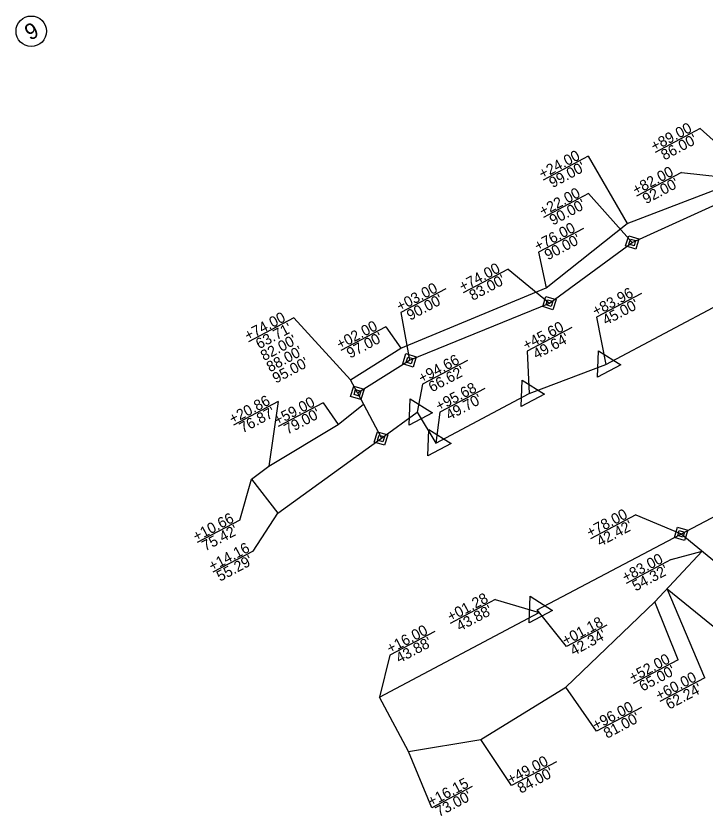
# Model space of a CAD drawing. Extents: x 1487704 to 1489071, y 498271 to 499440.
# Drawn here: x 1487703.5 to 1488029.1, y 498303.4 to 498681.2 of the extents above; entities that cross this region are included whole.
import ezdxf

# ---------------------------------------------------------------- set-up
doc = ezdxf.new("R2010")
doc.units = 0
for name, color, linetype in [('Prop Easement Construction', 7, 'Continuous'), ('Prop Easement Construction Station Offsets', 7, 'Continuous'), ('Prop Easement Permanent Drainage', 7, 'Continuous'), ('Prop Easement Permanent Drainage Station Offsets', 7, 'Continuous'), ('Prop Easement Temporary Drainage', 7, 'Continuous'), ('Prop Easement Temporary Drainage Station Offsets', 7, 'Continuous'), ('Prop ROW Marker CELL', 7, 'Continuous'), ('Prop ROW Permanent Easement CELL', 7, 'Continuous'), ('Prop ROW RW Lines', 7, 'Continuous'), ('Prop ROW Station Offsets', 7, 'Continuous'), ('Prop ROW Text', 7, 'Continuous')]:
    doc.layers.add(name, color=color, linetype=linetype)

msp = doc.modelspace()

# ---------------------------------------------------------------- linework, layer by layer
at = {"layer": 'Prop Easement Construction'}
for p, q in [((1487855.79, 498488.32), (1487867.65, 498497.99)), ((1487823.08, 498468.59), (1487855.79, 498488.32)), ((1487827.26, 498446.38), (1487876.21, 498481.82)), ((1487814.75, 498462.54), (1487823.08, 498468.59)), ((1487814.75, 498462.54), (1487827.26, 498446.38)), ((1488005.36, 498404.56), (1488027.76, 498428.5)), ((1487963.35, 498364.22), (1488005.36, 498404.56)), ((1487950.65, 498399.5), (1487949.84, 498400.81)), ((1487875.28, 498359.6), (1487950.65, 498399.5)), ((1487923.22, 498339.58), (1487963.35, 498364.22)), ((1487889.04, 498333.93), (1487875.28, 498359.6)), ((1487889.04, 498333.93), (1487923.22, 498339.58))]:
    msp.add_line(p, q, dxfattribs=at)
at = {"layer": 'Prop Easement Construction Station Offsets'}
for p, q in [((1487827.42, 498499.21), (1487806.24, 498488.02)), ((1487848.63, 498498.56), (1487827.37, 498487.33)), ((1487809.23, 498443.15), (1487789.11, 498432.53)), ((1487815.65, 498428.57), (1487796.59, 498418.51)), ((1488013.11, 498424.55), (1487991.86, 498413.3)), ((1487929.99, 498405.65), (1487908.74, 498394.4)), ((1487929.99, 498405.65), (1487950.65, 498399.5)), ((1487901.42, 498390.56), (1487880.17, 498379.31)), ((1487880.17, 498379.31), (1487875.28, 498359.6)), ((1488016.41, 498377.24), (1487995.16, 498365.99)), ((1487999.08, 498354.69), (1487977.82, 498343.44)), ((1487958.86, 498329.03), (1487937.61, 498317.77)), ((1487919.03, 498317.37), (1487900.02, 498307.34))]:
    msp.add_line(p, q, dxfattribs=at)
for points in [[(1487827.42, 498499.21), (1487823.08, 498468.59)], [(1487848.63, 498498.56), (1487855.79, 498488.32)], [(1487809.23, 498443.15), (1487814.75, 498462.54)], [(1487815.65, 498428.57), (1487827.26, 498446.38)], [(1488013.11, 498424.55), (1488027.76, 498428.5)], [(1488016.41, 498377.24), (1488005.36, 498404.56)], [(1487977.82, 498343.44), (1487963.35, 498364.22)], [(1487937.61, 498317.77), (1487923.22, 498339.58)], [(1487900.02, 498307.34), (1487889.04, 498333.93)]]:
    msp.add_lwpolyline(points, dxfattribs=at)
at = {"layer": 'Prop Easement Permanent Drainage'}
for p, q in [((1487994.71, 498574.3), (1488055.79, 498602.11)), ((1487955.56, 498545.66), (1487994.71, 498574.3)), ((1487889.53, 498518.63), (1487955.56, 498545.66)), ((1487864.84, 498503.29), (1487889.53, 498518.63)), ((1487864.84, 498503.29), (1487876.21, 498481.82)), ((1487876.21, 498481.82), (1487893.1, 498494.07)), ((1488017.78, 498436.68), (1488099.66, 498369.62))]:
    msp.add_line(p, q, dxfattribs=at)
at = {"layer": 'Prop Easement Permanent Drainage Station Offsets'}
for p, q in [((1488026.73, 498628.03), (1488005.46, 498616.8)), ((1487974.02, 498597.33), (1487952.76, 498586.1)), ((1487936.13, 498561.75), (1487914.87, 498550.53)), ((1487906.59, 498552.41), (1487885.32, 498541.18)), ((1487996.32, 498445.62), (1487975.05, 498434.39))]:
    msp.add_line(p, q, dxfattribs=at)
for points in [[(1488026.73, 498628.03), (1488055.79, 498602.11)], [(1487974.02, 498597.33), (1487994.71, 498574.3)], [(1487936.13, 498561.75), (1487955.56, 498545.66)], [(1487885.32, 498541.18), (1487889.53, 498518.63)], [(1487996.32, 498445.62), (1488017.78, 498436.68), (1488017.78, 498436.68)]]:
    msp.add_lwpolyline(points, dxfattribs=at)
at = {"layer": 'Prop Easement Temporary Drainage'}
for p, q in [((1487992.26, 498583.19), (1488046.8, 498604.14)), ((1487954.05, 498552.78), (1487992.26, 498583.19)), ((1487885.38, 498524.34), (1487954.05, 498552.78)), ((1487861.56, 498509.48), (1487885.38, 498524.34)), ((1487864.84, 498503.29), (1487861.56, 498509.48)), ((1488011.14, 498410.74), (1488060.72, 498370.51))]:
    msp.add_line(p, q, dxfattribs=at)
at = {"layer": 'Prop Easement Temporary Drainage Station Offsets'}
for p, q in [((1487973.86, 498615), (1487952.59, 498603.77)), ((1488018.02, 498607.38), (1487996.76, 498596.15)), ((1487971.68, 498580.88), (1487950.42, 498569.65)), ((1487834.87, 498538.67), (1487813.35, 498527.3)), ((1487878.21, 498534.5), (1487856.95, 498523.27)), ((1488028.97, 498368.67), (1488007.7, 498357.44))]:
    msp.add_line(p, q, dxfattribs=at)
for points in [[(1487973.86, 498615), (1487992.26, 498583.19)], [(1488018.02, 498607.38), (1488046.8, 498604.14)], [(1487950.42, 498569.65), (1487954.05, 498552.78), (1487954.05, 498552.78)], [(1487834.87, 498538.67), (1487861.56, 498509.48), (1487861.56, 498509.48)], [(1487878.21, 498534.5), (1487885.38, 498524.34)], [(1488028.97, 498368.67), (1488011.14, 498410.74)]]:
    msp.add_lwpolyline(points, dxfattribs=at)
at = {"layer": 'Prop ROW Marker CELL'}
for p, q in [((1487994.71, 498574.3), (1487994.71, 498574.3)), ((1487955.56, 498545.66), (1487955.56, 498545.66)), ((1487889.48, 498518.59), (1487889.48, 498518.59)), ((1487982.15, 498516.73), (1487982.15, 498516.73)), ((1487864.84, 498503.29), (1487864.84, 498503.29)), ((1487946.07, 498502.89), (1487946.07, 498502.89)), ((1487893.1, 498494.07), (1487893.1, 498494.07)), ((1487876.01, 498481.68), (1487876.01, 498481.68)), ((1487901.92, 498479.58), (1487901.92, 498479.58)), ((1488017.78, 498436.68), (1488017.78, 498436.68)), ((1487949.84, 498400.81), (1487949.84, 498400.81))]:
    msp.add_line(p, q, dxfattribs=at)
for points in [[(1487978.3, 498510.63), (1487978.78, 498523.1), (1487989.35, 498516.47)], [(1487942.22, 498496.79), (1487942.71, 498509.26), (1487953.28, 498502.63)], [(1487889.26, 498487.97), (1487889.74, 498500.43), (1487900.31, 498493.8)], [(1487898.07, 498473.48), (1487898.56, 498485.95), (1487909.13, 498479.31)], [(1487945.99, 498394.7), (1487946.48, 498407.17), (1487957.05, 498400.54)]]:
    msp.add_lwpolyline(points, close=True, dxfattribs=at)
at = {"layer": 'Prop ROW Permanent Easement CELL'}
for points in [[(1487993.03, 498577.48), (1487997.89, 498575.98), (1487996.39, 498571.12), (1487991.52, 498572.62)], [(1487993.87, 498575.89), (1487996.3, 498575.14), (1487995.55, 498572.71), (1487993.12, 498573.46)], [(1487953.88, 498548.84), (1487958.74, 498547.34), (1487957.24, 498542.47), (1487952.38, 498543.98)], [(1487954.72, 498547.25), (1487957.15, 498546.5), (1487956.4, 498544.07), (1487953.97, 498544.82)], [(1487887.8, 498521.78), (1487892.66, 498520.27), (1487891.16, 498515.41), (1487886.3, 498516.91)], [(1487888.64, 498520.18), (1487891.07, 498519.43), (1487890.32, 498517), (1487887.89, 498517.75)], [(1487863.16, 498506.47), (1487868.02, 498504.97), (1487866.52, 498500.11), (1487861.66, 498501.61)], [(1487864, 498504.88), (1487866.43, 498504.13), (1487865.68, 498501.7), (1487863.25, 498502.45)], [(1487874.33, 498484.86), (1487879.19, 498483.36), (1487877.69, 498478.49), (1487872.82, 498480)], [(1487875.17, 498483.27), (1487877.6, 498482.52), (1487876.85, 498480.09), (1487874.41, 498480.84)], [(1488016.09, 498439.86), (1488020.96, 498438.36), (1488019.46, 498433.49), (1488014.59, 498435)], [(1488016.93, 498438.27), (1488019.37, 498437.52), (1488018.62, 498435.09), (1488016.18, 498435.84)]]:
    msp.add_lwpolyline(points, close=True, dxfattribs=at)
at = {"layer": 'Prop ROW RW Lines'}
for p, q in [((1487982.15, 498516.73), (1488093.99, 498575.94)), ((1487946.07, 498502.89), (1487982.15, 498516.73)), ((1487901.92, 498479.58), (1487946.07, 498502.89)), ((1487893.1, 498494.07), (1487901.92, 498479.58)), ((1487949.84, 498400.81), (1488123.26, 498492.38))]:
    msp.add_line(p, q, dxfattribs=at)
at = {"layer": 'Prop ROW Station Offsets'}
for p, q in [((1487999.02, 498550.11), (1487977.84, 498538.93)), ((1487977.84, 498538.93), (1487982.15, 498516.73)), ((1487966.2, 498534.08), (1487945.02, 498522.9)), ((1487945.02, 498522.9), (1487946.07, 498502.89)), ((1487916.85, 498518.51), (1487895.68, 498507.3)), ((1487925, 498505.31), (1487903.82, 498494.1)), ((1487982.64, 498393.52), (1487963.58, 498383.43))]:
    msp.add_line(p, q, dxfattribs=at)
for points in [[(1487895.68, 498507.3), (1487893.1, 498494.07)], [(1487903.82, 498494.1), (1487901.92, 498479.58)], [(1487963.58, 498383.43), (1487949.84, 498400.81)]]:
    msp.add_lwpolyline(points, dxfattribs=at)
at = {"layer": 'Prop ROW Text'}
msp.add_line((1487710.75, 498674.03), (1487710.75, 498674.03), dxfattribs=at)
msp.add_circle((1487710.75, 498674.03), 7.2, dxfattribs=at)

# ---------------------------------------------------------------- texts
at = {"layer": 'Prop Easement Construction Station Offsets'}
for s, rotation, p in [('+20.86', 27.8351, (1487805.85, 498488.38)), ('+59.00', 27.8351, (1487827, 498487.7)), ("76.87'", 27.8351, (1487810.66, 498484.14)), ("79.00'", 27.8351, (1487831.83, 498483.46)), ('+10.66', 27.8351, (1487788.71, 498432.89)), ("75.42'", 27.8351, (1487792.99, 498428.36)), ('+14.16', 27.8351, (1487796.2, 498418.87)), ("55.29'", 27.8351, (1487799.95, 498414.06)), ('+83.00', 27.895, (1487991.49, 498413.68)), ("54.32'", 27.895, (1487996.32, 498409.44)), ('+01.28', 27.895, (1487908.91, 498395.06)), ("43.88'", 27.895, (1487913.2, 498390.54)), ('+16.00', 27.895, (1487880.34, 498379.96)), ("43.88'", 27.895, (1487884.63, 498375.45)), ('+52.00', 27.895, (1487994.79, 498366.36)), ("65.00'", 27.895, (1487999.62, 498362.13)), ('+96.00', 27.895, (1487977.46, 498343.81)), ("81.00'", 27.895, (1487982.82, 498339.86)), ('+49.00', 27.895, (1487937.24, 498318.15)), ("84.00'", 27.895, (1487942.07, 498313.91)), ('+16.15', 27.8351, (1487899.67, 498307.72)), ("73.00'", 27.8351, (1487903.35, 498302.88))]:
    msp.add_text(s, height=5, rotation=rotation, dxfattribs=at).set_placement(p)
at = {"layer": 'Prop Easement Permanent Drainage Station Offsets'}
for s, p in [('+89.00', (1488005.1, 498617.18)), ("86.00'", (1488009.92, 498612.94)), ('+22.00', (1487952.39, 498586.47)), ("90.00'", (1487957.21, 498582.23)), ('+74.00', (1487914.5, 498550.9)), ("83.00'", (1487919.33, 498546.66)), ('+03.00', (1487884.96, 498541.55)), ("90.00'", (1487889.78, 498537.31)), ('+78.00', (1487974.69, 498434.76)), ("42.42'", (1487979.51, 498430.52))]:
    msp.add_text(s, height=5, rotation=27.8351, dxfattribs=at).set_placement(p)
at = {"layer": 'Prop Easement Temporary Drainage Station Offsets'}
for s, p in [('+24.00', (1487952.23, 498604.14)), ("99.00'", (1487957.05, 498599.9)), ('+82.00', (1487996.4, 498596.52)), ("92.00'", (1488001.22, 498592.28)), ('+76.00', (1487950.05, 498570.03)), ("90.00'", (1487954.87, 498565.79)), ('+74.00', (1487813.11, 498527.74)), ("63.71'", (1487818.46, 498523.79)), ('+02.00', (1487856.58, 498523.64)), ("97.00'", (1487861.41, 498519.4)), ("82.00'", (1487820.74, 498518.2)), ("88.00'", (1487823.54, 498512.89)), ("95.00'", (1487826.34, 498507.59)), ('+60.00', (1488007.34, 498357.81)), ("62.24'", (1488012.16, 498353.57))]:
    msp.add_text(s, height=5, rotation=27.8351, dxfattribs=at).set_placement(p)
at = {"layer": 'Prop ROW Station Offsets'}
for s, rotation, p in [('+83.96', 27.8351, (1487977.45, 498539.29)), ("45.00'", 27.8351, (1487982.26, 498535.04)), ('+45.60', 27.8351, (1487944.61, 498523.25)), ("49.64'", 27.8351, (1487949.43, 498519.01)), ('+94.66', 27.895, (1487895.29, 498507.66)), ("66.62'", 27.895, (1487900.1, 498503.42)), ('+95.68', 27.895, (1487903.42, 498494.45)), ("49.70'", 27.895, (1487908.24, 498490.22)), ('+01.18', 27.895, (1487963.18, 498383.79)), ("42.34'", 27.895, (1487966.95, 498378.99))]:
    msp.add_text(s, height=5, rotation=rotation, dxfattribs=at).set_placement(p)
at = {"layer": 'Prop ROW Text'}
msp.add_text('9', height=7.5, rotation=27.4432, dxfattribs=at).set_placement((1487710.12, 498669.48))

doc.saveas('drawing.dxf')
